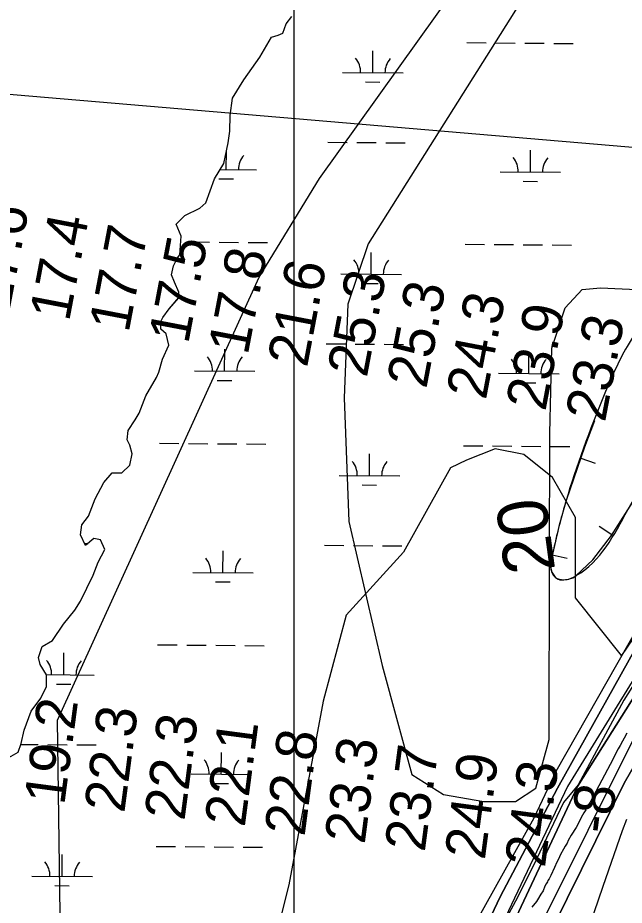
# Model space of a CAD drawing. Extents: x 3271442 to 3309282, y 752266 to 777610.
# Drawn here: x 3285621 to 3286622, y 761932 to 763397 of the extents above; entities that cross this region are included whole.
import ezdxf

# ---------------------------------------------------------------- set-up
doc = ezdxf.new("R2010")
doc.units = 0
for name, color, linetype in [('V-BORW-LINE', 7, 'Continuous'), ('V-GRID-MAJR', 7, 'Continuous'), ('V-RIVR-EDGE', 7, 'Continuous'), ('V-RIVR-RANG', 7, 'Continuous'), ('V-SITE-VEGE', 7, 'Continuous'), ('V-TOPO-DPTH', 7, 'Continuous'), ('V-TOPO-MINR', 7, 'Continuous'), ('V-TOPO-MINR-IDEN', 7, 'Continuous'), ('V-TOPO-WATR', 7, 'Continuous'), ('V-UTIL-LINE', 7, 'Continuous'), ('V-WETL-SWMP', 7, 'Continuous')]:
    doc.layers.add(name, color=color, linetype=linetype)

msp = doc.modelspace()

# ---------------------------------------------------------------- linework, layer by layer
at = {"layer": 'V-BORW-LINE'}
for p, q in [((3286550.2, 762670), (3286573.9, 762661.9)), ((3286601.6, 762543.6), (3286580.6, 762557.1)), ((3286503.2, 762510.4), (3286527.7, 762505.1))]:
    msp.add_line(p, q, dxfattribs=at)
msp.add_lwpolyline([(3286572.9, 762731.7), (3286556.4, 762687.9), (3286526.1, 762600.1), (3286514.6, 762559.6), (3286505.1, 762518.8), (3286500.1, 762496), (3286500.2, 762490.2), (3286502.5, 762481.6), (3286508.3, 762473.3), (3286510, 762471.7), (3286513.1, 762470), (3286515.5, 762469.3), (3286519, 762469.1), (3286522.5, 762469.3), (3286527.7, 762469.9), (3286531.6, 762470.6), (3286537.4, 762472.5), (3286540.2, 762474.1), (3286542.9, 762476.1), (3286570.1, 762502.1), (3286600.9, 762542.5), (3286628.1, 762584.8), (3286689.1, 762680.6), (3286710.5, 762713.6)], dxfattribs=at)
msp.add_spline([(3287493.6, 764311), (3287496.5, 764216.1), (3287433.3, 764060.9), (3287280.7, 763786.1), (3287241.3, 763729.2), (3287228, 763693.4), (3287286.2, 763705.8), (3287226.8, 763558.3), (3287072.3, 763274.5), (3286982.8, 763166.3), (3286836.9, 762895.4), (3286750.7, 762775.8), (3286628.1, 762584.8), (3286542.9, 762476.1), (3286522.5, 762469.3), (3286508.3, 762473.3), (3286505.1, 762518.8), (3286526.1, 762600.1), (3286589, 762774.6), (3286626.8, 762854.4), (3286717, 762982.7), (3286763, 763052.8), (3286849.1, 763163), (3286887.6, 763234.4), (3287021.5, 763430.5), (3287208.1, 763771), (3287255.9, 763817.4), (3287276.5, 763898.4), (3287311.4, 763982.3), (3287354.3, 764034.9), (3287423.9, 764171.9), (3287462.5, 764293.1), (3287493.6, 764311)], degree=3, dxfattribs=at)
at = {"layer": 'V-GRID-MAJR'}
msp.add_spline([(3286078, 757644.7), (3286077.1, 763703.6), (3286076.2, 769765.5), (3286075.4, 775827.4), (3286075.4, 775830.5)], degree=3, dxfattribs=at)
at = {"layer": 'V-RIVR-EDGE'}
msp.add_lwpolyline([(3286648.1, 762312.4), (3286621.5, 762270.3), (3286546, 762130.9), (3286522, 762101.4), (3286477, 762008.1), (3286446, 761944.7), (3286368.7, 761802.8), (3286348.1, 761762.4), (3286287.8, 761628.6), (3286246.7, 761536.6), (3286172, 761367.7), (3286137, 761298.2), (3286118.3, 761265.2), (3286105.6, 761228.8), (3286062.6, 761095.4), (3286046.8, 761036.8), (3286000, 760891.7), (3285982, 760843.5), (3285972.4, 760817), (3285961.9, 760803.1), (3285955.4, 760787.1), (3285955.3, 760763.2), (3285943.9, 760731.5), (3285923.4, 760670.6)], dxfattribs=at)
at = {"layer": 'V-SITE-VEGE'}
for points in [[(3285724.6, 762434), (3285745.7, 762476.9), (3285753.5, 762498.5), (3285764.7, 762519.4), (3285757.7, 762535.3), (3285746.4, 762537.2), (3285732.7, 762525.8), (3285724.7, 762543.5), (3285727, 762559.7), (3285737.7, 762574.3), (3285748.9, 762602.6), (3285762.9, 762630), (3285777, 762645.8), (3285792.8, 762645.7), (3285806.1, 762658.5), (3285809.8, 762677.2), (3285806.2, 762691.6), (3285801.8, 762700.4), (3285803.4, 762715.9), (3285814.8, 762733.1), (3285821.1, 762744.1), (3285832.3, 762773), (3285850.1, 762803.1), (3285853.8, 762811.9), (3285860.1, 762833.2), (3285870.1, 762856.7), (3285866.2, 762875), (3285857, 762882.8), (3285856.7, 762894.6), (3285860.4, 762902.3), (3285870.8, 762916.5), (3285886.7, 762934.9), (3285886.7, 762944), (3285879.8, 762960.6), (3285874.7, 762972.4), (3285878.1, 762987.4), (3285884.7, 763000.6), (3285888.4, 763005.8), (3285890.8, 763036.6), (3285882.4, 763056.1), (3285896.8, 763070.4), (3285921.5, 763082.4), (3285931.4, 763091.5), (3285945.6, 763131.2), (3285961.1, 763156.1), (3285968.3, 763190.6), (3285970.9, 763209.7), (3285971.4, 763235.8), (3285975.2, 763264.1), (3285994.1, 763294.5), (3286020.7, 763331.8), (3286040, 763364.8), (3286051, 763368.1), (3286058.4, 763371.3), (3286063.9, 763387.1), (3286073.5, 763398.8)], [(3285602.5, 762174), (3285621.7, 762185), (3285626.5, 762198.9), (3285631.8, 762220.9), (3285643.3, 762252.5), (3285658.8, 762273.7), (3285668.5, 762293.2), (3285668.2, 762312.3), (3285658, 762329.6), (3285655.1, 762341), (3285661.1, 762359.3), (3285678.4, 762369.2), (3285696.5, 762395.9), (3285715, 762419), (3285724.6, 762434)], [(3286626.5, 762216.2), (3286622.1, 762207.8), (3286619.1, 762202.9), (3286615.1, 762196), (3286612.1, 762190.1), (3286607.2, 762180.8), (3286603.7, 762173.9), (3286579.9, 762129.2), (3286570.9, 762111.6), (3286566, 762102.2), (3286562.5, 762097.3), (3286558.5, 762089.5), (3286555.5, 762084.6), (3286551.1, 762076.7), (3286548.1, 762070.8), (3286542.6, 762060.5), (3286534.7, 762047.7), (3286529.7, 762038.9), (3286527.7, 762034.5), (3286524.3, 762029.6), (3286521.8, 762024.6), (3286516.8, 762015.8), (3286513.8, 762008.4), (3286510.9, 762003), (3286506.9, 761994.2), (3286500.9, 761981.4), (3286497.9, 761975.5), (3286496, 761973.1), (3286495.4, 761970.6), (3286493, 761967.2), (3286491, 761963.3), (3286488, 761955.9), (3286484.5, 761950.5), (3286479.1, 761941.2), (3286477.1, 761938.2), (3286469.7, 761928.9)]]:
    msp.add_lwpolyline(points, dxfattribs=at)
at = {"layer": 'V-TOPO-DPTH'}
for points in [[(3290184.5, 766309.3), (3289787.2, 765875.4), (3289382.1, 765476.1), (3289095.6, 765248.1), (3288831.9, 764970.4), (3288488, 764620.5), (3288044.7, 764190.9), (3287922.4, 764069.2), (3287681.5, 763783.8), (3287413.7, 763403.3), (3287207.2, 763136.9), (3286958.6, 762805.9), (3286828.4, 762577.5), (3286545.2, 762128.3), (3286299.9, 761606.7), (3286162, 761328.7), (3286012.4, 760978.4), (3285889.5, 760586)], [(3285889.5, 760586), (3286012.4, 760978.4), (3286162, 761328.7), (3286299.9, 761606.7), (3286545.2, 762128.3), (3286828.4, 762577.5), (3286958.6, 762805.9), (3287207.2, 763136.9), (3287413.7, 763403.3), (3287681.5, 763783.8), (3287922.4, 764069.2), (3288044.7, 764190.9), (3288488, 764620.5), (3288831.9, 764970.4), (3289095.6, 765248.1), (3289382.1, 765476.1), (3289787.2, 765875.4), (3290184.5, 766309.3)], [(3290020.8, 766206.6), (3289516.8, 765666.5), (3289074, 765275.5), (3288708.6, 764917.4), (3288315.4, 764501.4), (3287891.9, 764079.9), (3287686.9, 763845.7), (3287395.9, 763426.6), (3287290.6, 763288.8), (3286966.5, 762864.3), (3286883.3, 762737.5), (3286664.3, 762398.4), (3286511.8, 762125.3), (3286417.4, 761946.1), (3286125.9, 761331), (3285984.3, 761013.7), (3285859, 760583.2)], [(3290114.4, 766120.7), (3289718.5, 765685.4), (3289162.2, 765192.4), (3288544.9, 764616.8), (3288268, 764319.2), (3287999.4, 764016.1), (3287467.7, 763415.4), (3287029.8, 762786.8), (3286810.8, 762461.5), (3286622.2, 762133.3), (3286222.6, 761325.2), (3286050.3, 760916.9), (3285958.5, 760643.7)], [(3285958.5, 760643.7), (3286050.3, 760916.9), (3286222.6, 761325.2), (3286622.2, 762133.3), (3286810.8, 762461.5), (3287029.8, 762786.8), (3287467.7, 763415.4), (3287999.4, 764016.1), (3288268, 764319.2), (3288544.9, 764616.8), (3289162.2, 765192.4), (3289718.5, 765685.4), (3290114.4, 766120.7)]]:
    msp.add_lwpolyline(points, dxfattribs=at)
at = {"layer": 'V-TOPO-MINR'}
for points in [[(3290158.8, 766323.3), (3289801.9, 765939.2), (3289577.6, 765696.8), (3289342.4, 765481.9), (3289093.4, 765283.7), (3288869.1, 765041.3), (3288642, 764809.8), (3288448.2, 764606), (3287900.1, 764066.1), (3287673, 763796), (3287365.4, 763363.2), (3287074.5, 762982.8), (3286955.3, 762825.7), (3286916.5, 762762.3), (3286708.6, 762420.3), (3286528.3, 762128.1), (3286389.5, 761835.7), (3286139.7, 761319.9), (3286031.4, 761063.3), (3285992.5, 760980.6), (3285886.7, 760621.8)], [(3290214.1, 766293.6), (3289929.1, 765972), (3289602.4, 765641.5), (3289131.9, 765217.3), (3288509, 764619.6), (3288066.1, 764170.6), (3287952.5, 764027.3), (3287426.2, 763396.2), (3286982.9, 762795.2), (3286686.2, 762304.4), (3286189.4, 761308.7), (3286031, 760925.2), (3285942, 760663.1)], [(3285859, 760583.2), (3285984.3, 761013.7), (3286125.9, 761331), (3286417.4, 761946.1), (3286511.8, 762125.3), (3286664.3, 762398.4), (3286883.3, 762737.5), (3286966.5, 762864.3), (3287290.6, 763288.8), (3287395.9, 763426.6), (3287686.9, 763845.7), (3287891.9, 764079.9), (3288315.4, 764501.4), (3288708.6, 764917.4), (3289074, 765275.5), (3289516.8, 765666.5), (3290020.8, 766206.6)], [(3285958.5, 760643.7), (3286050.3, 760916.9), (3286222.6, 761325.2), (3286622.2, 762133.3), (3286810.8, 762461.5), (3287029.8, 762786.8), (3287467.7, 763415.4), (3287999.4, 764016.1), (3288268, 764319.2), (3288544.9, 764616.8), (3289162.2, 765192.4), (3289718.5, 765685.4), (3290114.4, 766120.7)], [(3286661.6, 762420.5), (3286509.1, 762153), (3286473, 762075.7), (3286276, 761722.7), (3286131.7, 761413.8), (3286095.6, 761336.6), (3286059.6, 761300.7), (3285979.5, 761287.1), (3285921.5, 761287.3), (3285847, 761309.6), (3285783.6, 761353.9), (3285720.7, 761616.4), (3285691.1, 761917.5), (3285686.3, 762237.8), (3286019.5, 762968.8), (3286119.3, 763131.5), (3286507.3, 763674.6), (3286978.4, 764322.4)], [(3286759, 763845.2), (3286590.1, 763644), (3286199.2, 763023.6), (3286165.8, 762924.3), (3286159.9, 762769.7), (3286167.6, 762565.3), (3286222.3, 762327.6), (3286271.6, 762148), (3286323.9, 762114.8), (3286390.2, 762103.5), (3286442.7, 762103.4), (3286475.9, 762125.4), (3286498.1, 762205.5), (3286498.9, 762498.2), (3286499.4, 762710.8), (3286502.5, 762851.7), (3286524.8, 762917.9), (3286552.5, 762948.2), (3286582.8, 762950.9), (3286654.6, 762947.9)], [(3286625.9, 762073.6), (3286618.6, 762055), (3286586.9, 761963.2), (3286564.6, 761898.4), (3286264.9, 761327.7), (3285769.1, 760020.8)]]:
    msp.add_lwpolyline(points, dxfattribs=at)
at = {"layer": 'V-TOPO-WATR'}
msp.add_lwpolyline([(3290184.5, 766309.3), (3289787.2, 765875.4), (3289382.1, 765476.1), (3289095.6, 765248.1), (3288831.9, 764970.4), (3288488, 764620.5), (3288044.7, 764190.9), (3287922.4, 764069.2), (3287681.5, 763783.8), (3287413.7, 763403.3), (3287207.2, 763136.9), (3286958.6, 762805.9), (3286828.4, 762577.5), (3286545.2, 762128.3), (3286299.9, 761606.7), (3286162, 761328.7), (3286012.4, 760978.4), (3285889.5, 760586)], dxfattribs=at)
at = {"layer": 'V-UTIL-LINE'}
msp.add_lwpolyline([(3284681, 763349.6), (3290442.2, 762860), (3294363.6, 762975), (3296343, 765526.6)], dxfattribs=at)
at = {"layer": 'V-WETL-SWMP'}
for p, q in [((3286063.9, 763387.1), (3286073.5, 763398.8)), ((3286058.4, 763371.3), (3286063.9, 763387.1)), ((3286040, 763364.8), (3286051, 763368.1)), ((3286051, 763368.1), (3286058.4, 763371.3)), ((3286020.7, 763331.8), (3286040, 763364.8)), ((3286362, 763355.8), (3286394, 763355.5)), ((3286410, 763355.4), (3286442, 763355.1)), ((3286458, 763355), (3286490, 763354.7)), ((3286506, 763354.6), (3286538, 763354.3)), ((3286207, 763306.3), (3286207.3, 763342.3)), ((3285994.1, 763294.5), (3286020.7, 763331.8)), ((3285975.2, 763264.1), (3285994.1, 763294.5)), ((3286157, 763306.7), (3286257, 763305.9)), ((3286194.9, 763291), (3286218.9, 763290.8)), ((3285971.4, 763235.8), (3285975.2, 763264.1)), ((3285970.9, 763209.7), (3285971.4, 763235.8)), ((3285968.3, 763190.6), (3285970.9, 763209.7)), ((3285961.1, 763156.1), (3285968.3, 763190.6)), ((3286132.7, 763191.5), (3286164.7, 763191.2)), ((3286180.7, 763191.1), (3286212.7, 763190.8)), ((3286228.7, 763190.7), (3286260.7, 763190.4)), ((3285965.2, 763146.4), (3285965.5, 763177.1)), ((3286467.1, 763142.3), (3286467.4, 763178.3)), ((3285945.6, 763131.2), (3285961.1, 763156.1)), ((3285955.2, 763146.5), (3286015.2, 763146)), ((3286417.1, 763142.7), (3286517.1, 763141.9)), ((3285931.4, 763091.5), (3285945.6, 763131.2)), ((3285953.1, 763131.1), (3285977.1, 763130.9)), ((3286455, 763127), (3286479, 763126.8)), ((3285921.5, 763082.4), (3285931.4, 763091.5)), ((3285896.8, 763070.4), (3285921.5, 763082.4)), ((3285882.4, 763056.1), (3285896.8, 763070.4)), ((3285890.8, 763036.6), (3285882.4, 763056.1)), ((3285888.4, 763005.8), (3285890.8, 763036.6)), ((3285905.4, 763026.9), (3285937.4, 763026.6)), ((3285953.4, 763026.5), (3285985.4, 763026.2)), ((3286001.4, 763026.1), (3286033.4, 763025.8)), ((3286359.3, 763023.1), (3286391.3, 763022.9)), ((3286407.3, 763022.7), (3286439.3, 763022.5)), ((3286455.3, 763022.3), (3286487.3, 763022.1)), ((3286503.3, 763021.9), (3286535.3, 763021.7)), ((3285878.1, 762987.4), (3285884.7, 763000.6)), ((3285884.7, 763000.6), (3285888.4, 763005.8)), ((3286204.3, 762973.6), (3286204.6, 763009.6)), ((3285874.7, 762972.4), (3285878.1, 762987.4)), ((3285879.8, 762960.6), (3285874.7, 762972.4)), ((3286154.3, 762974.1), (3286254.3, 762973.2)), ((3285886.7, 762944), (3285879.8, 762960.6)), ((3286192.2, 762958.3), (3286216.1, 762958.1)), ((3285886.7, 762934.8), (3285886.7, 762944)), ((3285870.8, 762916.5), (3285886.7, 762934.8)), ((3285860.4, 762902.3), (3285870.8, 762916.5)), ((3285856.7, 762894.6), (3285860.4, 762902.3)), ((3285857, 762882.8), (3285856.7, 762894.6)), ((3285866.2, 762875), (3285857, 762882.8)), ((3285870.1, 762856.7), (3285866.2, 762875)), ((3285860.1, 762833.2), (3285870.1, 762856.7)), ((3286129.9, 762858.8), (3286161.9, 762858.6)), ((3286177.9, 762858.4), (3286209.9, 762858.2)), ((3286225.9, 762858), (3286257.9, 762857.8)), ((3285962.5, 762813.8), (3285962.8, 762849.8)), ((3286464.4, 762809.6), (3286464.7, 762845.6)), ((3285853.8, 762811.9), (3285860.1, 762833.2)), ((3285850.1, 762803.1), (3285853.8, 762811.9)), ((3285912.5, 762814.2), (3286012.5, 762813.4)), ((3286414.4, 762810.1), (3286514.4, 762809.2)), ((3286939.1, 762818.2), (3286617.3, 762344.5)), ((3285832.3, 762773), (3285850.1, 762803.1)), ((3285950.4, 762798.4), (3285974.4, 762798.2)), ((3286452.2, 762794.3), (3286476.2, 762794.1)), ((3285821.1, 762744.1), (3285832.3, 762773)), ((3285814.8, 762733.1), (3285821.1, 762744.1)), ((3285803.4, 762715.9), (3285814.8, 762733.1)), ((3285801.8, 762700.4), (3285803.4, 762715.9)), ((3285806.2, 762691.6), (3285801.8, 762700.4)), ((3285854.7, 762694.6), (3285886.6, 762694.3)), ((3285902.6, 762694.2), (3285934.6, 762693.9)), ((3285950.6, 762693.8), (3285982.6, 762693.5)), ((3285998.6, 762693.4), (3286030.6, 762693.1)), ((3285809.8, 762677.2), (3285806.2, 762691.6)), ((3286356.5, 762690.5), (3286388.5, 762690.2)), ((3286409, 762685.6), (3286361.7, 762666.6)), ((3286404.5, 762690.1), (3286436.5, 762689.8)), ((3286456.3, 762676.1), (3286409, 762685.6)), ((3286452.5, 762689.7), (3286484.5, 762689.4)), ((3286500.5, 762689.3), (3286532.5, 762689)), ((3285806.1, 762658.5), (3285809.8, 762677.2)), ((3286201.5, 762641), (3286201.8, 762677)), ((3286361.7, 762666.6), (3286335.5, 762654.2)), ((3286503.7, 762638.2), (3286456.3, 762676.1)), ((3285792.8, 762645.7), (3285806.1, 762658.5)), ((3286335.5, 762654.2), (3286257.6, 762515.1)), ((3285762.9, 762630), (3285777, 762645.8)), ((3285777, 762645.8), (3285792.8, 762645.7)), ((3286151.5, 762641.4), (3286251.5, 762640.6)), ((3286541.5, 762571.9), (3286503.7, 762638.2)), ((3285748.9, 762602.6), (3285762.9, 762630)), ((3286189.4, 762625.7), (3286213.4, 762625.5)), ((3285737.7, 762574.3), (3285748.9, 762602.6)), ((3285727, 762559.7), (3285737.7, 762574.3)), ((3286541.5, 762439.3), (3286541.5, 762571.9)), ((3285724.7, 762543.5), (3285727, 762559.7)), ((3285732.7, 762525.8), (3285724.7, 762543.5)), ((3285746.4, 762537.2), (3285732.7, 762525.8)), ((3285757.7, 762535.3), (3285746.4, 762537.2)), ((3285764.7, 762519.4), (3285757.7, 762535.3)), ((3285731.1, 762529.4), (3285737, 762529.4)), ((3285753.5, 762498.5), (3285764.7, 762519.4)), ((3285959.7, 762481.1), (3285960, 762517.1)), ((3286127.2, 762526.2), (3286159.2, 762525.9)), ((3286175.2, 762525.8), (3286207.2, 762525.5)), ((3286223.2, 762525.4), (3286255.2, 762525.1)), ((3286257.6, 762515.1), (3286162.9, 762410.8)), ((3285745.7, 762476.9), (3285753.5, 762498.5)), ((3285724.6, 762434), (3285745.7, 762476.9)), ((3285909.7, 762481.5), (3286009.7, 762480.7)), ((3285947.6, 762465.8), (3285971.6, 762465.6)), ((3285715, 762419), (3285724.6, 762434)), ((3286617.3, 762344.5), (3286541.5, 762439.3)), ((3285696.5, 762395.9), (3285715, 762419)), ((3286162.9, 762410.8), (3286125, 762268.7)), ((3285678.4, 762369.2), (3285696.5, 762395.9)), ((3285655.1, 762341), (3285661.1, 762359.3)), ((3285661.1, 762359.3), (3285678.4, 762369.2)), ((3285851.9, 762361.9), (3285883.9, 762361.7)), ((3285899.9, 762361.5), (3285931.9, 762361.3)), ((3285947.9, 762361.1), (3285979.9, 762360.9)), ((3285995.9, 762360.7), (3286027.9, 762360.5)), ((3285658, 762329.6), (3285655.1, 762341)), ((3285696.9, 762312.5), (3285697.2, 762348.5)), ((3285668.2, 762312.3), (3285658, 762329.6)), ((3285667.9, 762312.7), (3285746.9, 762312)), ((3285668.5, 762293.2), (3285668.2, 762312.3)), ((3285684.8, 762297.1), (3285708.8, 762296.9)), ((3285658.8, 762273.7), (3285668.5, 762293.2)), ((3285643.3, 762252.5), (3285658.8, 762273.7)), ((3286125, 762268.7), (3286068.2, 761965.6)), ((3285631.8, 762220.9), (3285643.3, 762252.5)), ((3285626.5, 762198.9), (3285631.8, 762220.9)), ((3285621.7, 762185), (3285626.5, 762198.9)), ((3285626.1, 762197.6), (3285654.5, 762197.4)), ((3285670.5, 762197.2), (3285702.5, 762197)), ((3285718.5, 762196.8), (3285750.5, 762196.6)), ((3285602.5, 762174), (3285621.7, 762185)), ((3285957, 762148.4), (3285957.3, 762184.4)), ((3285907, 762148.9), (3286007, 762148)), ((3285944.9, 762133.1), (3285968.9, 762132.9)), ((3285849.2, 762029.3), (3285881.2, 762029)), ((3285897.2, 762028.9), (3285929.2, 762028.6)), ((3285945.2, 762028.5), (3285977.2, 762028.2)), ((3285993.2, 762028.1), (3286025.2, 762027.8)), ((3285694.2, 761979.8), (3285694.5, 762015.8)), ((3285644.2, 761980.2), (3285744.2, 761979.4)), ((3285682, 761964.5), (3285706, 761964.3)), ((3286068.2, 761965.6), (3285992.5, 761662.4))]:
    msp.add_line(p, q, dxfattribs=at)
for centre, start, end in [((3286151.8, 763307.2), 358.7563, 40.2999), ((3286262.3, 763306.3), 138.7563, 180.2999), ((3286020.5, 763146.5), 138.7563, 180.2999), ((3286411.9, 763143.2), 358.7563, 40.2999), ((3286522.4, 763142.3), 138.7563, 180.2999), ((3286149, 762974.6), 358.7563, 40.2999), ((3286259.5, 762973.7), 138.7563, 180.2999), ((3285907.2, 762814.7), 358.7563, 40.2999), ((3286017.7, 762813.8), 138.7563, 180.2999), ((3286409.1, 762810.6), 358.7563, 40.2999), ((3286519.6, 762809.7), 138.7563, 180.2999), ((3286146.3, 762641.9), 358.7563, 40.2999), ((3286256.8, 762641), 138.7563, 180.2999), ((3285904.5, 762482), 358.7563, 40.2999), ((3286015, 762481.1), 138.7563, 180.2999), ((3285641.7, 762313.4), 358.7563, 40.2999), ((3285752.2, 762312.5), 138.7563, 180.2999), ((3285901.8, 762149.4), 358.7563, 40.2999), ((3286012.2, 762148.5), 138.7563, 180.2999), ((3285638.9, 761980.7), 358.7563, 40.2999), ((3285749.4, 761979.8), 138.7563, 180.2999)]:
    msp.add_arc(centre, 35.2, start, end, dxfattribs=at)

# ---------------------------------------------------------------- texts
at = {"layer": 'V-RIVR-RANG'}
for s, rotation, p in [('17.6', 79.2183, (3285607, 762910.7)), ('17.4', 79.2183, (3285705.6, 762894)), ('17.7', 79.2183, (3285803.9, 762875.6)), ('17.5', 79.2183, (3285902.2, 762857.1)), ('17.8', 79.2183, (3286000.5, 762838.6)), ('21.6', 79.2183, (3286098.4, 762818.4)), ('25.3', 79.2183, (3286197, 762801.7)), ('25.3', 79.2183, (3286295.3, 762783.3)), ('24.3', 79.2183, (3286393.6, 762764.8)), ('23.9', 79.2183, (3286491.8, 762746.1)), ('23.3', 79.2183, (3286590.2, 762727.9)), ('19.2', 82.4583, (3285697.7, 762096.1)), ('22.3', 82.4583, (3285796.8, 762083.2)), ('22.3', 82.4583, (3285896, 762070.4)), ('22.1', 82.4583, (3285995.5, 762059.8)), ('22.8', 82.4583, (3286094.3, 762044.6)), ('23.3', 82.4583, (3286193.5, 762031.7)), ('23.7', 82.4583, (3286292.7, 762018.8)), ('24.9', 82.4583, (3286391.8, 762005.7)), ('24.3', 82.4583, (3286491, 761993)), ('-8', 82.7374, (3286599.5, 762048.5))]:
    msp.add_text(s, height=67, rotation=rotation, dxfattribs=at).set_placement(p)
at = {"layer": 'V-TOPO-MINR-IDEN'}
msp.add_text('20', height=83, rotation=97.5841, dxfattribs=at).set_placement((3286508.2, 762485.3))

doc.saveas('drawing.dxf')
